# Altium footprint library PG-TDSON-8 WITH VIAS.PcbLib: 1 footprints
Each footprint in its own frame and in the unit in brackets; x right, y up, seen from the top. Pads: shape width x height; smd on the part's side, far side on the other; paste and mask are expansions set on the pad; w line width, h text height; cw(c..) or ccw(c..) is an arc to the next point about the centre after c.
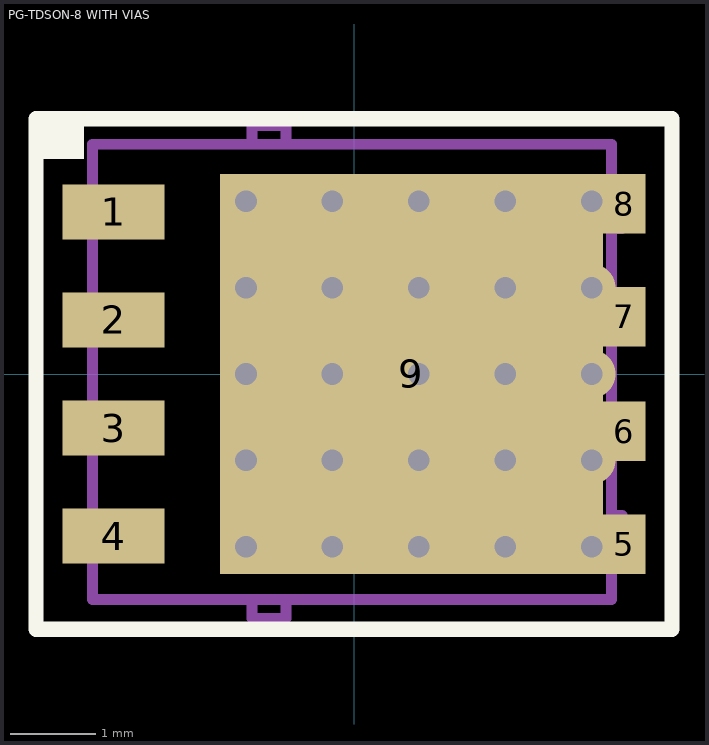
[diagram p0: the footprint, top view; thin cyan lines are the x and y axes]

## PG-TDSON-8 WITH VIAS [mm] "Infineon recommended land pattern"
height 1.1
pads (9):
  rect 1.2x0.65 smd: 1(-2.825,1.905) 2(-2.825,0.635) 3(-2.825,-0.635) 4(-2.825,-1.905)
  rect 0.5x0.7 smd: 5(3.175,-2) 6(3.175,-0.675) 7(3.175,0.675) 8(3.175,2)
  rect 4.5x4.7 smd paste-2.25: 9(0.675,0)
via -1.27,0 diameter 0.559 hole 0.254
via -0.254,0 diameter 0.559 hole 0.254
via 0.762,0 diameter 0.559 hole 0.254
via 1.778,0 diameter 0.559 hole 0.254
via -1.27,-1.016 diameter 0.559 hole 0.254
via -1.27,-2.032 diameter 0.559 hole 0.254
via -1.27,1.016 diameter 0.559 hole 0.254
via -1.27,2.032 diameter 0.559 hole 0.254
via -0.254,2.032 diameter 0.559 hole 0.254
via -0.254,1.016 diameter 0.559 hole 0.254
via -0.254,-1.016 diameter 0.559 hole 0.254
via -0.254,-2.032 diameter 0.559 hole 0.254
via 0.762,-1.016 diameter 0.559 hole 0.254
via 0.762,1.016 diameter 0.559 hole 0.254
via 0.762,2.032 diameter 0.559 hole 0.254
via 1.778,1.016 diameter 0.559 hole 0.254
via 1.778,2.032 diameter 0.559 hole 0.254
via 1.778,-1.016 diameter 0.559 hole 0.254
via 0.762,-2.032 diameter 0.559 hole 0.254
via 1.778,-2.032 diameter 0.559 hole 0.254
via 2.794,-2.032 diameter 0.559 hole 0.254
via 2.794,-1.016 diameter 0.559 hole 0.254
via 2.794,0 diameter 0.559 hole 0.254
via 2.794,1.016 diameter 0.559 hole 0.254
via 2.794,2.032 diameter 0.559 hole 0.254
Top Overlay:
  rectangle: -3.74,2.528 -3.175,2.975
  lines w0.178: -3.74,-3 -0.105,-3 3.74,-3 3.74,0 3.74,3 0.105,3 -3.74,3 -3.74,0 -3.74,-3
Top Paste:
  rectangle: -1.475,-2.25 -0.242,-0.95
  rectangle: 0.058,-2.25 1.291,-0.95
  rectangle: 1.591,-2.25 2.824,-0.95
  rectangle: 1.591,-0.65 2.824,0.65
  rectangle: 0.058,-0.65 1.291,0.65
  rectangle: -1.475,-0.65 -0.242,0.65
  rectangle: 1.591,0.95 2.824,2.25
  rectangle: 0.058,0.95 1.291,2.25
  rectangle: -1.475,0.95 -0.242,2.25
M5 Assembly Top:
  rectangle: -3.74,2.528 -3.175,2.975
  lines w0.127: -3.075,-2.1 -3.2,-2.1 -3.2,-1.66 -3.075,-1.66 ; -3.075,-0.83 -3.2,-0.83 -3.2,-0.39 -3.075,-0.39 ; -3.075,0.44 -3.2,0.44 -3.2,0.88 -3.075,0.88 ; -3.075,1.71 -3.2,1.71 -3.2,2.15 -3.075,2.15 ; -1.2,-2.65 -1.2,-2.87 -0.8,-2.87 -0.8,-2.65 ; -1.2,2.7 -1.2,2.92 -0.8,2.92 -0.8,2.7 ; 3.025,-2.1 3.15,-2.1 3.15,-1.66 3.025,-1.66 ; 3.025,-0.83 3.15,-0.83 3.15,-0.39 3.025,-0.39 ; 3.025,0.44 3.15,0.44 3.15,0.88 3.025,0.88 ; 3.025,1.71 3.15,1.71 3.15,2.15 3.025,2.15 ; -3.075,-2.65 -3.075,2.7 3.025,2.7 3.025,-2.65 -3.075,-2.65
  text ".Designator" at -1.925,-0.5 h1.02
3D body: height 1.1, standoff 0, extent -3.175,-2.895 3.175,2.895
